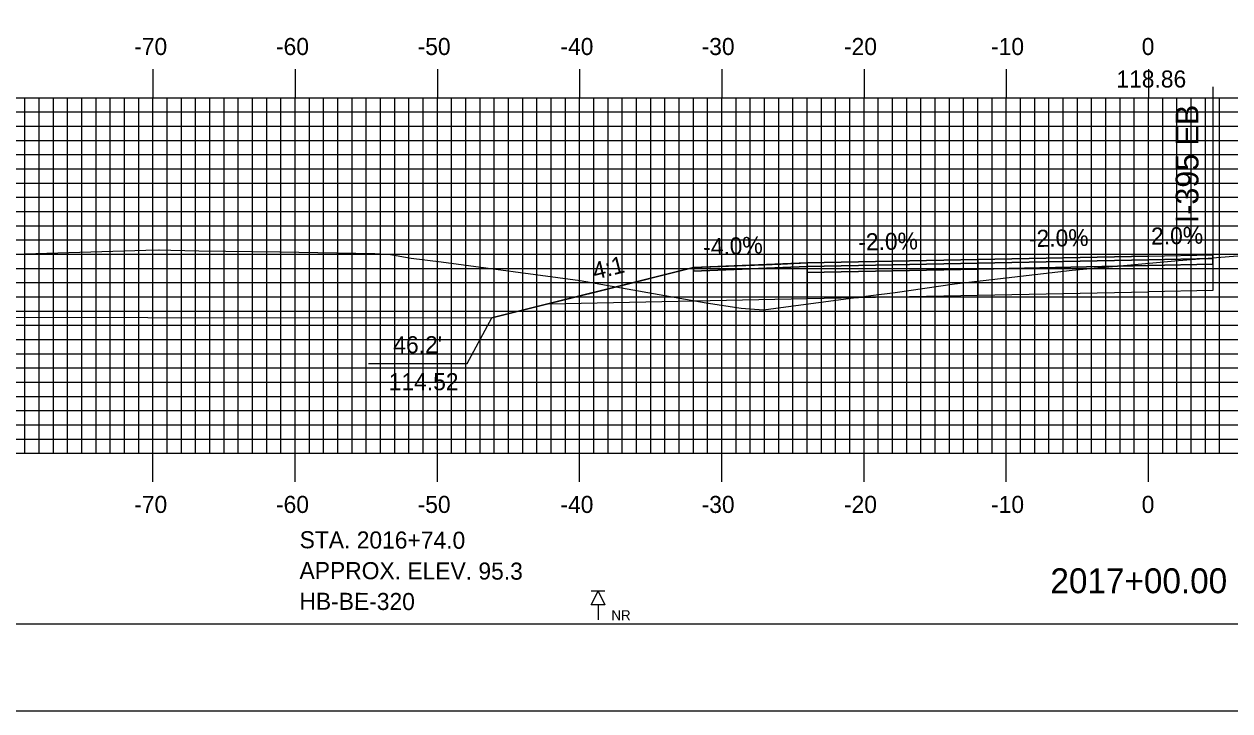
# Model space of a CAD drawing. Extents: x 855074 to 855418, y 366605 to 366825.
# Drawn here: x 855161 to 855245.8, y 366604.9 to 366653.2 of the extents above; entities that cross this region are included whole.
import ezdxf

# ---------------------------------------------------------------- set-up
doc = ezdxf.new("R2010")
doc.units = 0
for name, color, linetype in [('ANNOTATION', 7, 'Continuous'), ('BORDER', 7, 'Continuous'), ('BORING - NO REFUSAL', 7, 'Continuous'), ('D_Roadway_Centerline', 7, 'Continuous'), ('D_Roadway_Centerline_Text', 7, 'Continuous'), ('D_Roadway_Edge_Shoulder', 7, 'Continuous'), ('D_Roadway_Edge_TW', 7, 'Continuous'), ('D_Roadway_Pavement', 7, 'Continuous'), ('D_Roadway_SlopeLines', 7, 'Continuous'), ('D_Roadway_SubGrade', 7, 'Continuous'), ('H_V ANNOTATION', 7, 'Continuous'), ('M_Roadway_Centerline', 7, 'Continuous'), ('MAJOR', 7, 'Continuous'), ('MINOR', 7, 'Continuous'), ('PLOT BOUNDARY', 7, 'Continuous'), ('S_Roadway_Centerline', 7, 'Continuous')]:
    doc.layers.add(name, color=color, linetype=linetype)

msp = doc.modelspace()

# ---------------------------------------------------------------- linework, layer by layer
at = {"layer": 'ANNOTATION'}
msp.add_lwpolyline([(855185.236, 366629.36), (855192.165, 366629.36), (855193.895, 366632.57)], dxfattribs=at)
at = {"layer": 'BORDER'}
msp.add_lwpolyline([(855090.469, 366611.055), (855410.469, 366611.055), (855410.469, 366821.055), (855090.469, 366821.055)], close=True, dxfattribs=at)
at = {"layer": 'BORING - NO REFUSAL'}
for p, q in [((855201.849, 366613.355), (855200.89, 366613.355)), ((855201.369, 366612.396), (855201.369, 366611.337))]:
    msp.add_line(p, q, dxfattribs=at)
msp.add_lwpolyline([(855201.369, 366613.355), (855201.849, 366612.396), (855200.89, 366612.396)], close=True, dxfattribs=at)
at = {"layer": 'D_Roadway_Centerline'}
msp.add_lwpolyline([(855121.285, 366632.643), (855193.895, 366632.57), (855193.895, 366632.57), (855194.457, 366632.711), (855197.169, 366633.389), (855197.171, 366633.389), (855201.825, 366634.553), (855208.07, 366636.114), (855208.073, 366636.114), (855214.211, 366636.36), (855216.07, 366636.434), (855228.067, 366636.674), (855228.069, 366636.674), (855240.065, 366636.914), (855240.069, 366636.914), (855240.071, 366636.914), (855244.592, 366637.004)], dxfattribs=at)
at = {"layer": 'D_Roadway_Edge_Shoulder'}
for points in [[(855240.069, 366636.914), (855244.592, 366637.004), (855244.592, 366636.754), (855240.069, 366636.664)], [(855216.07, 366636.434), (855208.07, 366636.114), (855208.07, 366635.864), (855216.07, 366636.184)]]:
    msp.add_lwpolyline(points, close=True, dxfattribs=at)
at = {"layer": 'D_Roadway_Edge_TW'}
for points in [[(855240.069, 366636.914), (855228.069, 366636.674), (855228.069, 366636.424), (855240.069, 366636.664)], [(855228.069, 366636.674), (855216.07, 366636.434), (855216.07, 366636.184), (855228.069, 366636.424)]]:
    msp.add_lwpolyline(points, close=True, dxfattribs=at)
at = {"layer": 'D_Roadway_Pavement'}
for points in [[(855240.069, 366636.664), (855244.592, 366636.754), (855244.592, 366636.338), (855240.069, 366636.247)], [(855228.069, 366636.424), (855216.07, 366636.184), (855216.07, 366635.767), (855228.069, 366636.007)], [(855240.069, 366636.664), (855228.069, 366636.424), (855228.069, 366636.007), (855240.069, 366636.247)]]:
    msp.add_lwpolyline(points, close=True, dxfattribs=at)
for points in [[(855216.07, 366636.184), (855216.07, 366635.767)], [(855216.07, 366636.184), (855216.07, 366635.767)], [(855228.069, 366636.424), (855228.069, 366636.007)]]:
    msp.add_lwpolyline(points, dxfattribs=at)
at = {"layer": 'D_Roadway_SlopeLines'}
msp.add_line((855208.07, 366636.114), (855193.895, 366632.57), dxfattribs=at)
at = {"layer": 'D_Roadway_SubGrade'}
msp.add_line((855244.592, 366648.813), (855244.592, 366637.004), dxfattribs=at)
for points in [[(855240.069, 366636.247), (855244.592, 366636.338), (855244.592, 366636.754), (855244.592, 366637.004), (855244.592, 366634.504), (855240.069, 366634.414)], [(855216.07, 366635.767), (855216.07, 366636.184), (855208.07, 366635.864), (855208.07, 366636.114), (855197.896, 366633.57), (855216.07, 366633.934)], [(855228.069, 366636.007), (855216.07, 366635.767), (855216.07, 366633.934), (855228.069, 366634.174)], [(855240.069, 366636.247), (855228.069, 366636.007), (855228.069, 366634.174), (855240.069, 366634.414)]]:
    msp.add_lwpolyline(points, close=True, dxfattribs=at)
at = {"layer": 'MAJOR'}
for p, q in [((855170.069, 366650.059), (855170.069, 366648.055)), ((855180.069, 366650.059), (855180.069, 366648.055)), ((855190.069, 366650.059), (855190.069, 366648.055)), ((855200.069, 366650.059), (855200.069, 366648.055)), ((855210.069, 366650.059), (855210.069, 366648.055)), ((855220.069, 366650.059), (855220.069, 366648.055)), ((855230.069, 366650.059), (855230.069, 366648.055)), ((855240.069, 366650.059), (855240.069, 366648.055)), ((855100.069, 366648.055), (855380.069, 366648.055)), ((855100.069, 366648.055), (855380.069, 366648.055)), ((855170.069, 366623.055), (855170.069, 366648.055)), ((855180.069, 366623.055), (855180.069, 366648.055)), ((855190.069, 366623.055), (855190.069, 366648.055)), ((855200.069, 366623.055), (855200.069, 366648.055)), ((855210.069, 366623.055), (855210.069, 366648.055)), ((855220.069, 366623.055), (855220.069, 366648.055)), ((855230.069, 366623.055), (855230.069, 366648.055)), ((855240.069, 366623.055), (855240.069, 366648.055)), ((855100.069, 366643.055), (855380.069, 366643.055)), ((855100.069, 366638.055), (855380.069, 366638.055)), ((855100.069, 366633.055), (855380.069, 366633.055)), ((855100.069, 366628.055), (855380.069, 366628.055)), ((855100.069, 366623.055), (855380.069, 366623.055)), ((855100.069, 366623.055), (855380.069, 366623.055)), ((855170.069, 366621.051), (855170.069, 366623.055)), ((855180.069, 366621.051), (855180.069, 366623.055)), ((855190.069, 366621.051), (855190.069, 366623.055)), ((855200.069, 366621.051), (855200.069, 366623.055)), ((855210.069, 366621.051), (855210.069, 366623.055)), ((855220.069, 366621.051), (855220.069, 366623.055)), ((855230.069, 366621.051), (855230.069, 366623.055)), ((855240.069, 366621.051), (855240.069, 366623.055))]:
    msp.add_line(p, q, dxfattribs=at)
at = {"layer": 'MINOR'}
for p, q in [((855161.069, 366623.055), (855161.069, 366648.055)), ((855162.069, 366623.055), (855162.069, 366648.055)), ((855163.069, 366623.055), (855163.069, 366648.055)), ((855164.069, 366623.055), (855164.069, 366648.055)), ((855165.069, 366623.055), (855165.069, 366648.055)), ((855166.069, 366623.055), (855166.069, 366648.055)), ((855167.069, 366623.055), (855167.069, 366648.055)), ((855168.069, 366623.055), (855168.069, 366648.055)), ((855169.069, 366623.055), (855169.069, 366648.055)), ((855171.069, 366623.055), (855171.069, 366648.055)), ((855172.069, 366623.055), (855172.069, 366648.055)), ((855173.069, 366623.055), (855173.069, 366648.055)), ((855174.069, 366623.055), (855174.069, 366648.055)), ((855175.069, 366623.055), (855175.069, 366648.055)), ((855176.069, 366623.055), (855176.069, 366648.055)), ((855177.069, 366623.055), (855177.069, 366648.055)), ((855178.069, 366623.055), (855178.069, 366648.055)), ((855179.069, 366623.055), (855179.069, 366648.055)), ((855181.069, 366623.055), (855181.069, 366648.055)), ((855182.069, 366623.055), (855182.069, 366648.055)), ((855183.069, 366623.055), (855183.069, 366648.055)), ((855184.069, 366623.055), (855184.069, 366648.055)), ((855185.069, 366623.055), (855185.069, 366648.055)), ((855186.069, 366623.055), (855186.069, 366648.055)), ((855187.069, 366623.055), (855187.069, 366648.055)), ((855188.069, 366623.055), (855188.069, 366648.055)), ((855189.069, 366623.055), (855189.069, 366648.055)), ((855191.069, 366623.055), (855191.069, 366648.055)), ((855192.069, 366623.055), (855192.069, 366648.055)), ((855193.069, 366623.055), (855193.069, 366648.055)), ((855194.069, 366623.055), (855194.069, 366648.055)), ((855195.069, 366623.055), (855195.069, 366648.055)), ((855196.069, 366623.055), (855196.069, 366648.055)), ((855197.069, 366623.055), (855197.069, 366648.055)), ((855198.069, 366623.055), (855198.069, 366648.055)), ((855199.069, 366623.055), (855199.069, 366648.055)), ((855201.069, 366623.055), (855201.069, 366648.055)), ((855202.069, 366623.055), (855202.069, 366648.055)), ((855203.069, 366623.055), (855203.069, 366648.055)), ((855204.069, 366623.055), (855204.069, 366648.055)), ((855205.069, 366623.055), (855205.069, 366648.055)), ((855206.069, 366623.055), (855206.069, 366648.055)), ((855207.069, 366623.055), (855207.069, 366648.055)), ((855208.069, 366623.055), (855208.069, 366648.055)), ((855209.069, 366623.055), (855209.069, 366648.055)), ((855211.069, 366623.055), (855211.069, 366648.055)), ((855212.069, 366623.055), (855212.069, 366648.055)), ((855213.069, 366623.055), (855213.069, 366648.055)), ((855214.069, 366623.055), (855214.069, 366648.055)), ((855215.069, 366623.055), (855215.069, 366648.055)), ((855216.069, 366623.055), (855216.069, 366648.055)), ((855217.069, 366623.055), (855217.069, 366648.055)), ((855218.069, 366623.055), (855218.069, 366648.055)), ((855219.069, 366623.055), (855219.069, 366648.055)), ((855221.069, 366623.055), (855221.069, 366648.055)), ((855222.069, 366623.055), (855222.069, 366648.055)), ((855223.069, 366623.055), (855223.069, 366648.055)), ((855224.069, 366623.055), (855224.069, 366648.055)), ((855225.069, 366623.055), (855225.069, 366648.055)), ((855226.069, 366623.055), (855226.069, 366648.055)), ((855227.069, 366623.055), (855227.069, 366648.055)), ((855228.069, 366623.055), (855228.069, 366648.055)), ((855229.069, 366623.055), (855229.069, 366648.055)), ((855231.069, 366623.055), (855231.069, 366648.055)), ((855232.069, 366623.055), (855232.069, 366648.055)), ((855233.069, 366623.055), (855233.069, 366648.055)), ((855234.069, 366623.055), (855234.069, 366648.055)), ((855235.069, 366623.055), (855235.069, 366648.055)), ((855236.069, 366623.055), (855236.069, 366648.055)), ((855237.069, 366623.055), (855237.069, 366648.055)), ((855238.069, 366623.055), (855238.069, 366648.055)), ((855239.069, 366623.055), (855239.069, 366648.055)), ((855241.069, 366623.055), (855241.069, 366648.055)), ((855242.069, 366623.055), (855242.069, 366648.055)), ((855243.069, 366623.055), (855243.069, 366648.055)), ((855244.069, 366623.055), (855244.069, 366648.055)), ((855245.069, 366623.055), (855245.069, 366648.055)), ((855100.069, 366647.055), (855380.069, 366647.055)), ((855100.069, 366646.055), (855380.069, 366646.055)), ((855100.069, 366645.055), (855380.069, 366645.055)), ((855100.069, 366644.055), (855380.069, 366644.055)), ((855100.069, 366642.055), (855380.069, 366642.055)), ((855100.069, 366641.055), (855380.069, 366641.055)), ((855100.069, 366640.055), (855380.069, 366640.055)), ((855100.069, 366639.055), (855380.069, 366639.055)), ((855100.069, 366637.055), (855380.069, 366637.055)), ((855100.069, 366636.055), (855380.069, 366636.055)), ((855100.069, 366635.055), (855380.069, 366635.055)), ((855100.069, 366634.055), (855380.069, 366634.055)), ((855100.069, 366632.055), (855380.069, 366632.055)), ((855100.069, 366631.055), (855380.069, 366631.055)), ((855100.069, 366630.055), (855380.069, 366630.055)), ((855100.069, 366629.055), (855380.069, 366629.055)), ((855100.069, 366627.055), (855380.069, 366627.055)), ((855100.069, 366626.055), (855380.069, 366626.055)), ((855100.069, 366625.055), (855380.069, 366625.055)), ((855100.069, 366624.055), (855380.069, 366624.055))]:
    msp.add_line(p, q, dxfattribs=at)
at = {"layer": 'PLOT BOUNDARY'}
msp.add_lwpolyline([(855074.283, 366604.937), (855414.283, 366604.937), (855414.283, 366824.937), (855074.283, 366824.937)], close=True, dxfattribs=at)
at = {"layer": 'S_Roadway_Centerline'}
msp.add_lwpolyline([(855154.063, 366636.86), (855169.573, 366637.331), (855170.473, 366637.346), (855170.518, 366637.349), (855171.325, 366637.339), (855173.297, 366637.293), (855178.997, 366637.224), (855185.67, 366637.096), (855186.779, 366637.036), (855188.217, 366636.775), (855190.329, 366636.522), (855200.109, 366635.2), (855208.968, 366633.632), (855211.425, 366633.261), (855212.993, 366633.135), (855220.554, 366634.134), (855222.25, 366634.358), (855226.428, 366634.962), (855234.69, 366635.918), (855242.18, 366636.596), (855246.931, 366636.992)], dxfattribs=at)

# ---------------------------------------------------------------- texts
at = {"layer": 'ANNOTATION'}
for s, height, rotation, p in [('I-395 EB', 1.6, 90, (855243.579, 366639.231)), ('-2.0%', 1.2, 1.14577, (855219.674, 366637.307)), ('-2.0%', 1.2, 1.14577, (855231.673, 366637.547)), ('2.0%', 1.2, 1.13993, (855240.259, 366637.718)), ('-4.0%', 1.2, 2.29058, (855208.774, 366636.944)), ('4:1', 1.2, 14.03748, (855201.156, 366635.247)), ("46.2' ", 1.2, 360, (855186.97, 366630.086)), ('114.52', 1.2, 360, (855186.649, 366627.486))]:
    msp.add_text(s, height=height, rotation=rotation, dxfattribs=at).set_placement(p)
at = {"layer": 'BORING - NO REFUSAL'}
for s, p in [('STA. 2016+74.0', (855180.383, 366616.372)), ('APPROX. ELEV. 95.3', (855180.376, 366614.212)), ('HB-BE-320', (855180.369, 366612.052))]:
    msp.add_text(s, height=1.2, rotation=359.81416, dxfattribs=at).set_placement(p)
msp.add_text('NR', height=0.6998, dxfattribs=at).set_placement((855202.302, 366611.316))
at = {"layer": 'D_Roadway_Centerline_Text'}
msp.add_text('118.86', height=1.2, dxfattribs=at).set_placement((855237.81, 366648.768))
at = {"layer": 'H_V ANNOTATION'}
for s, height, p in [('-70', 1.2, (855168.753, 366651.055)), ('-60', 1.2, (855178.721, 366651.055)), ('-50', 1.2, (855188.678, 366651.055)), ('-40', 1.2, (855198.721, 366651.055)), ('-30', 1.2, (855208.646, 366651.055)), ('-20', 1.2, (855218.656, 366651.055)), ('-10', 1.2, (855228.999, 366651.055)), ('0', 1.2, (855239.588, 366651.055)), ('-70', 1.2, (855168.753, 366618.855)), ('-60', 1.2, (855178.721, 366618.855)), ('-50', 1.2, (855188.678, 366618.855)), ('-40', 1.2, (855198.721, 366618.855)), ('-30', 1.2, (855208.646, 366618.855)), ('-20', 1.2, (855218.656, 366618.855)), ('-10', 1.2, (855228.999, 366618.855)), ('0', 1.2, (855239.588, 366618.855)), ('2017+00.00', 1.75, (855233.171, 366613.211))]:
    msp.add_text(s, height=height, dxfattribs=at).set_placement(p)
at = {"layer": 'M_Roadway_Centerline'}
for s, p in [('C', (855170.513, 366637.349)), ('L', (855170.518, 366637.342))]:
    msp.add_text(s, height=0.0146, dxfattribs=at).set_placement(p)

doc.saveas('drawing.dxf')
